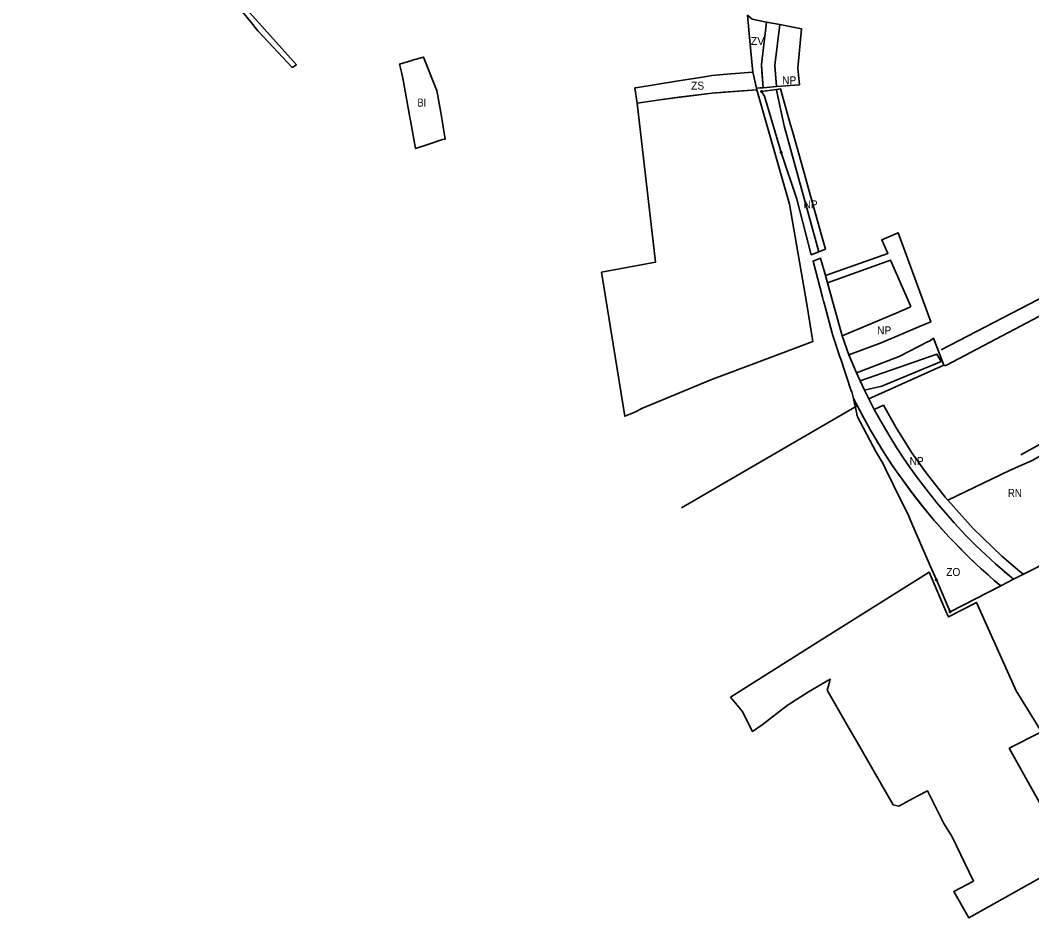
# Model space of a CAD drawing. Extents: x -650276 to -642489, y -1074311 to -1066720.
# Drawn here: x -650258 to -648741, y -1071627 to -1070281 of the extents above; entities that cross this region are included whole.
import ezdxf

# ---------------------------------------------------------------- set-up
doc = ezdxf.new("R2010")
doc.units = 0
doc.header["$LTSCALE"] = 4.8
doc.header["$PDMODE"] = 32
doc.header["$PDSIZE"] = 2.4
for name, color, linetype, lineweight in [('2', 7, 'Continuous', 35), ('24', 7, 'Continuous', 35), ('40', 7, 'Continuous', 35), ('41', 7, 'Continuous', 35), ('42', 7, 'Continuous', 35), ('48', 7, 'Continuous', 35), ('54', 7, 'Continuous', 35), ('7', 7, 'Continuous', 35)]:
    doc.layers.add(name, color=color, linetype=linetype, lineweight=lineweight)
doc.layers.add('62', color=7, linetype='Continuous')

msp = doc.modelspace()

# ---------------------------------------------------------------- linework, layer by layer
at = {"layer": '2'}
for points in [[(-649678.92, -1070395.81), (-649672.83, -1070429.29), (-649672.49, -1070431.16), (-649664.82, -1070473.32), (-649644.74, -1070466.68), (-649640.18, -1070465.2), (-649624.33, -1070460.03), (-649620.17, -1070459.09), (-649624.97, -1070431.24), (-649627.13, -1070419.17), (-649633, -1070386.46), (-649635.52, -1070380.14), (-649653.03, -1070336.2), (-649669.24, -1070341.04), (-649670.28, -1070341.35), (-649689.02, -1070346.94), (-649685.31, -1070360.88), (-649683.08, -1070373.11)], [(-649332.2, -1070405.42), (-649294.79, -1070399.65), (-649220.16, -1070390.26), (-649153.11, -1070385.21), (-649104, -1070557), (-649078, -1070707), (-649069, -1070763), (-649118.07, -1070781.42), (-649221.94, -1070820.12), (-649289.37, -1070848.48), (-649324.21, -1070862.51), (-649335.72, -1070868.73), (-649351, -1070875), (-649386, -1070659), (-649305, -1070644)], [(-649192.568, -1071295.954), (-649055.64, -1071209.682), (-648966.9, -1071154.34), (-648894.684, -1071108.668), (-648867.88, -1071170.58), (-648865.61, -1071175.825), (-648823.531, -1071154.018), (-648764.17, -1071286.65), (-648725.85, -1071348.28), (-648774.371, -1071372.773), (-648749.854, -1071416.727), (-648680.709, -1071540.691), (-648835.095, -1071627.059), (-648857.66, -1071587.83), (-648827.998, -1071572.04), (-648859.97, -1071505.55), (-648872.28, -1071485.58), (-648893.65, -1071443.47), (-648897.169, -1071436.535), (-648912.69, -1071444.48), (-648940.23, -1071459.65), (-648948.27, -1071457.92), (-648976.99, -1071408.03), (-649002.42, -1071363.86), (-649015.83, -1071340.58), (-649031.91, -1071312.65), (-649047.3, -1071285.92), (-649045.19, -1071277.86), (-649042.927, -1071269.216), (-649075.6, -1071288.29), (-649107.36, -1071308.9), (-649144.99, -1071337.61), (-649159.64, -1071347.68), (-649175.1, -1071317.29)]]:
    msp.add_lwpolyline(points, close=True, dxfattribs=at)
at = {"layer": '24'}
msp.add_line((-649146.163, -1070347.543), (-649145.424, -1070357.637), dxfattribs=at)
for points in [[(-649138.43, -1070283.6), (-649146.163, -1070347.543), (-649146.163, -1070347.543), (-649145.424, -1070357.637)], [(-649125.503, -1070355.837), (-649126.069, -1070348.097), (-649118.257, -1070287.455), (-649138.43, -1070283.6), (-649146.163, -1070347.543)], [(-649125.503, -1070355.837), (-649126.069, -1070348.097), (-649118.257, -1070287.455), (-649138.43, -1070283.6)], [(-649145.424, -1070357.637), (-649143.633, -1070382.123), (-649123.693, -1070380.572), (-649125.503, -1070355.837)], [(-649145.424, -1070357.637), (-649143.633, -1070382.123), (-649123.693, -1070380.572), (-649125.503, -1070355.837)], [(-649059.951, -1070628.223), (-649112.14, -1070439.152), (-649123.138, -1070388.16), (-649123.385, -1070384.775), (-649145.73, -1070387.91)], [(-649145.73, -1070387.91), (-649141.48, -1070394.84), (-649132.07, -1070426.81), (-649116.56, -1070479.19)], [(-649116.56, -1070479.19), (-649093.2, -1070549.1), (-649071.33, -1070632.6), (-649059.951, -1070628.223)]]:
    msp.add_lwpolyline(points, dxfattribs=at)
msp.add_lwpolyline([(-648976.834, -1070864.527), (-648985.145, -1070848.538), (-648991.386, -1070835.954), (-648998.132, -1070821.723), (-649003.641, -1070809.566), (-649014.888, -1070782.994), (-649025.129, -1070754.377), (-649047.11, -1070674.743), (-649050.081, -1070663.981), (-649057.338, -1070637.689), (-649068.65, -1070642.23), (-649068.65, -1070642.23), (-649054.31, -1070696.44), (-649052.77, -1070702.25), (-649052.44, -1070703.48), (-649051.03, -1070708.74), (-649040.03, -1070750.06), (-649039.38, -1070752.51), (-649039.06, -1070753.72), (-649038.51, -1070755.38), (-649027.74, -1070787.51), (-649027.64, -1070787.8), (-649019.48, -1070812.18), (-649018.48, -1070815.18), (-649011.24, -1070836.79), (-649010.67, -1070838.5), (-649007.885, -1070848.153), (-648994.464, -1070873.974), (-648982.467, -1070895.704), (-648970.712, -1070915.663), (-648960.268, -1070932.429), (-648949.389, -1070949.031), (-648939.232, -1070963.818), (-648918.601, -1070991.969), (-648896.068, -1071020.184), (-648886.874, -1071031.044), (-648874.793, -1071044.773), (-648863.847, -1071056.723), (-648851.175, -1071069.886), (-648838.696, -1071082.562), (-648823.087, -1071097.562), (-648816.379, -1071103.782), (-648806.239, -1071112.938), (-648797, -1071121), (-648790.23, -1071126.818), (-648787.207, -1071129.363), (-648767.824, -1071119.455), (-648771.725, -1071116.233), (-648781.806, -1071107.721), (-648795.407, -1071095.8), (-648824.292, -1071068.677), (-648839.273, -1071053.556), (-648856.883, -1071034.761), (-648869.629, -1071020.411), (-648880.44, -1071007.703), (-648894.164, -1070990.806), (-648902.714, -1070979.812), (-648912.396, -1070966.893), (-648922.92, -1070952.242), (-648932.78, -1070937.887), (-648943.414, -1070921.659), (-648953.605, -1070905.299), (-648965.093, -1070885.794)], close=True, dxfattribs=at)
for p in [(-649145.73, -1070387.91), (-649116.56, -1070479.19)]:
    msp.add_point(p, dxfattribs=at)
at = {"layer": '40'}
msp.add_lwpolyline([(-649138.43, -1070283.6), (-649159.78, -1070279.52), (-649166.86, -1070273.48), (-649162.91, -1070317.47), (-649159.19, -1070358.82), (-649153.64, -1070382.9), (-649148.23, -1070382.48), (-649143.633, -1070382.123), (-649146.163, -1070347.543)], close=True, dxfattribs=at)
at = {"layer": '41'}
msp.add_lwpolyline([(-649159.19, -1070358.82), (-649197.91, -1070361.8), (-649203.4, -1070362.23), (-649220.47, -1070363.94), (-649231.39, -1070365.69), (-649273.57, -1070372.44), (-649304.18, -1070377.35), (-649331.3, -1070381.69), (-649335.79, -1070382.41), (-649332.2, -1070405.42), (-649294.79, -1070399.65), (-649269.769, -1070396.502), (-649220.16, -1070390.26), (-649202.969, -1070388.965), (-649153.11, -1070385.21), (-649153.64, -1070382.9)], close=True, dxfattribs=at)
at = {"layer": '42'}
for p, q in [((-648883.73, -1071120.13), (-648862.97, -1071168.09)), ((-648862.97, -1071168.09), (-648787.207, -1071129.363))]:
    msp.add_line(p, q, dxfattribs=at)
for points in [[(-649002.97, -1070857.609), (-649007.885, -1070848.153), (-649003.1, -1070871.35), (-649002.82, -1070872.69), (-649002.62, -1070873.69), (-649002.15, -1070875.96), (-648974.4, -1070927.77), (-648963.5, -1070946.45), (-648959.92, -1070953.73), (-648948.29, -1070977.37), (-648924.92, -1071024.89), (-648922.98, -1071029.49), (-648921.87, -1071032.04), (-648892.82, -1071099.15), (-648883.73, -1071120.13)], [(-648994.42, -1070874.053), (-648994.464, -1070873.974), (-648994.52, -1070873.867)], [(-648982.403, -1070895.812), (-648982.467, -1070895.704), (-648982.524, -1070895.601)], [(-648970.64, -1070915.778), (-648970.712, -1070915.663), (-648970.771, -1070915.564)], [(-648960.194, -1070932.542), (-648960.268, -1070932.429), (-648960.34, -1070932.313)], [(-648949.345, -1070949.096), (-648949.389, -1070949.031), (-648949.428, -1070948.972)], [(-648939.179, -1070963.89), (-648939.232, -1070963.818), (-648939.33, -1070963.675)], [(-648918.464, -1070992.141), (-648918.601, -1070991.969), (-648918.737, -1070991.784)]]:
    msp.add_lwpolyline(points, dxfattribs=at)
for start, end in [(206.85611, 208.07207), (208.08607, 209.71957), (209.73567, 211.25686), (211.27351, 212.56631), (212.58435, 213.8879), (213.89777, 215.07157), (215.08899, 217.38409), (217.41391, 230.04071)]:
    msp.add_arc((-648232.695, -1070467.567), 863.398, start, end, dxfattribs=at)
for p in [(-648883.73, -1071120.13), (-648862.97, -1071168.09)]:
    msp.add_point(p, dxfattribs=at)
at = {"layer": '48'}
msp.add_line((-648894.164, -1070990.806), (-648880.44, -1071007.703), dxfattribs=at)
for points in [[(-649924.15, -1070268.55), (-649913.03, -1070282.44), (-649901.59, -1070296.73), (-649871.28, -1070329.01), (-649850.04, -1070351.64), (-649843.513, -1070347.685), (-650257.713, -1069885.547)], [(-649089.07, -1070377.88), (-649091.46, -1070352.73), (-649086.157, -1070293.589), (-649118.257, -1070287.455), (-649126.069, -1070348.097)], [(-649126.069, -1070348.097), (-649123.693, -1070380.572), (-649089.07, -1070377.88)], [(-648866.341, -1071000.881), (-648870.479, -1070996.265), (-648900.337, -1070957.964), (-648920.293, -1070929.567), (-648944.376, -1070891.404), (-648963.107, -1070858.328), (-648976.834, -1070864.527)], [(-648976.834, -1070864.527), (-648965.093, -1070885.794), (-648953.605, -1070905.299), (-648943.414, -1070921.659), (-648932.78, -1070937.887), (-648922.92, -1070952.242), (-648912.396, -1070966.893), (-648894.164, -1070990.806)], [(-648880.44, -1071007.703), (-648869.629, -1071020.411), (-648856.883, -1071034.761), (-648839.273, -1071053.556), (-648824.292, -1071068.677), (-648795.407, -1071095.8), (-648777.641, -1071111.238), (-648771.725, -1071116.233), (-648767.824, -1071119.455), (-648752.967, -1071111.861), (-648758.423, -1071107.756), (-648785.386, -1071084.634), (-648828.353, -1071043.265), (-648866.341, -1071000.881)]]:
    msp.add_lwpolyline(points, dxfattribs=at)
for points in [[(-649059.951, -1070628.223), (-649049.96, -1070624.38), (-649055.93, -1070603.08), (-649058.38, -1070594.33), (-649065.42, -1070569.21), (-649072.47, -1070544.09), (-649079.51, -1070518.97), (-649086.55, -1070493.85), (-649093.59, -1070468.73), (-649100.01, -1070445.82), (-649102.31, -1070437.61), (-649109.76, -1070411.05), (-649117.36, -1070383.93), (-649123.385, -1070384.775), (-649123.138, -1070388.16), (-649112.14, -1070439.152)], [(-649014.888, -1070782.994), (-648966.35, -1070764.7), (-648908.94, -1070740.19), (-648892.215, -1070733.293), (-648927.2, -1070637.98), (-648941.064, -1070599.735), (-648965.569, -1070610.382), (-648956.687, -1070630.825), (-649050.081, -1070663.981), (-649047.11, -1070674.743), (-648952.455, -1070640.564), (-648922.196, -1070710.207), (-648924.668, -1070712.022), (-648943.837, -1070720.104), (-649025.129, -1070754.377)], [(-648985.145, -1070848.538), (-648872.375, -1070798.112), (-648874.87, -1070791.61), (-648887.84, -1070757.84), (-648894.08, -1070762.22), (-648896.11, -1070762.73), (-648939.5, -1070785.4), (-649003.641, -1070809.566), (-648998.132, -1070821.723), (-648882.919, -1070781.673), (-648876.64, -1070792.6), (-648965.475, -1070829.829), (-648991.386, -1070835.954)]]:
    msp.add_lwpolyline(points, close=True, dxfattribs=at)
at = {"layer": '54'}
for p, q in [((-648876.429, -1070775.252), (-648558.121, -1070610.206)), ((-649003.638, -1070859.543), (-649266.084, -1071012.071))]:
    msp.add_line(p, q, dxfattribs=at)
for points in [[(-648433.898, -1070569.36), (-648868.299, -1070798.03), (-648871.326, -1070799.464)], [(-648756.915, -1070932.76), (-648403.845, -1070737.419), (-648368.964, -1070716.905), (-648263.103, -1070807.79), (-648213.358, -1070823.563), (-648181.392, -1070823.076), (-647966.625, -1070675.686), (-647777.125, -1070608.309)]]:
    msp.add_lwpolyline(points, dxfattribs=at)
at = {"layer": '7'}
msp.add_lwpolyline([(-648866.341, -1071000.881), (-648828.353, -1071043.265), (-648785.386, -1071084.634), (-648758.423, -1071107.756), (-648752.967, -1071111.861), (-648734.849, -1071102.599), (-648651.375, -1071057.109), (-648627.39, -1071042.65), (-648655.76, -1070997.5), (-648634.07, -1070983.17), (-648571.14, -1070944.67), (-648540.7, -1070928.6), (-648479.18, -1070891.26), (-648386.587, -1070833.807), (-648427.25, -1070767.95), (-648511.09, -1070814.7), (-648721.54, -1070930.88), (-648740.25, -1070941.21), (-648774.23, -1070956.42)], close=True, dxfattribs=at)

# ---------------------------------------------------------------- texts
at = {"layer": '62'}
msp.add_text('ZV', height=12, dxfattribs=at).set_placement((-649162.076, -1070318.026))
for s, width, p in [('ZS', 0.95, (-649251.482, -1070385.05)), ('NP', 0.95, (-649115.076, -1070377.026)), ('BI', 0.85, (-649661.845, -1070410.442)), ('NP', 0.95, (-649082.942, -1070563.157)), ('NP', 0.95, (-648972.583, -1070752.041)), ('NP', 0.95, (-648923.942, -1070948.157)), ('RN', 0.9, (-648776.428, -1070995.883)), ('ZO', 0.95, (-648868.886, -1071114.486))]:
    msp.add_text(s, height=12, dxfattribs=dict(at, width=width)).set_placement(p)

doc.saveas('drawing.dxf')
